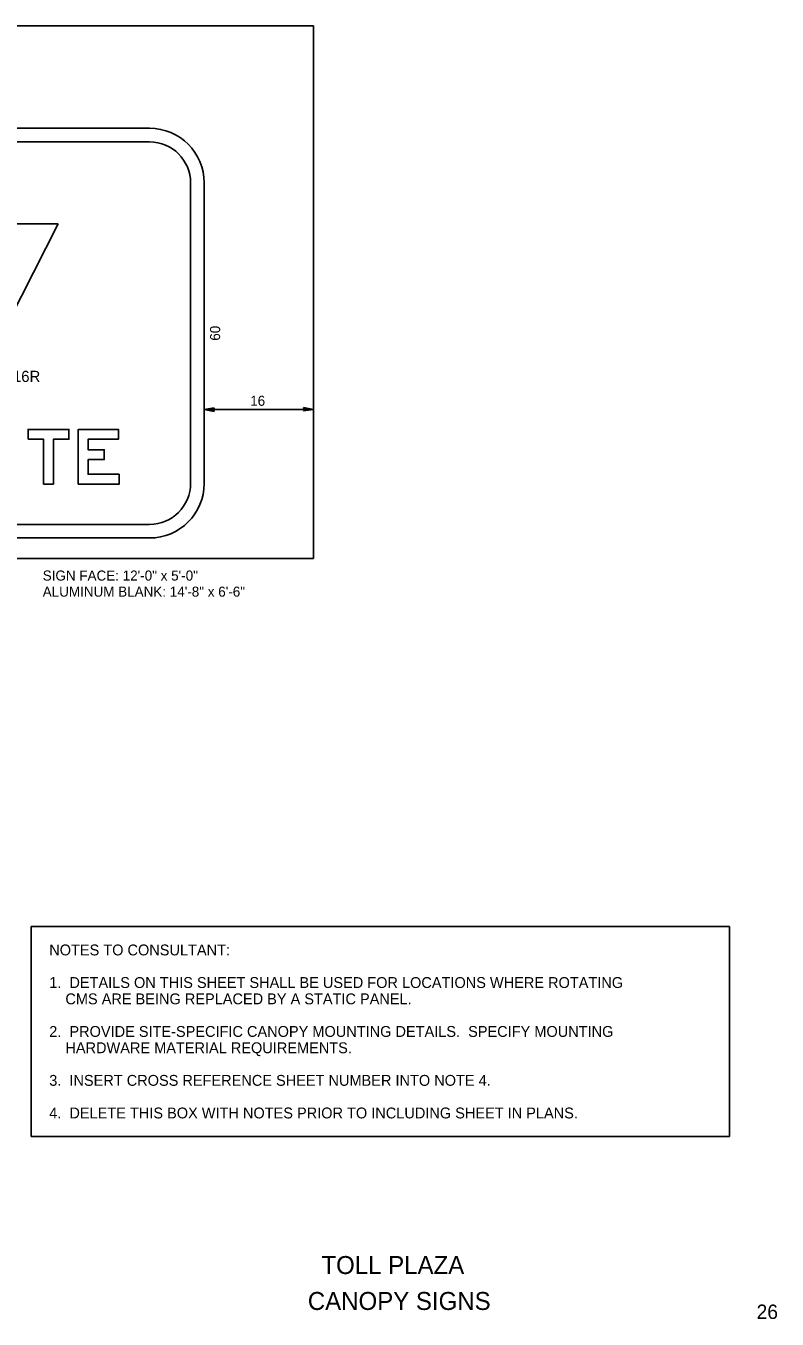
# Model space of a CAD drawing. Extents: x 60714 to 61340, y 9359 to 9729.
# Drawn here: x 61130.7 to 61339.9, y 9369.1 to 9729 of the extents above; entities that cross this region are included whole.
import ezdxf

# ---------------------------------------------------------------- set-up
doc = ezdxf.new("R2010")
doc.units = 0
for name, color, linetype in [('1', 7, 'Continuous'), ('2', 7, 'Continuous'), ('52', 7, 'Continuous'), ('GSBWFill', 7, 'Continuous'), ('SignPanel', 7, 'Continuous'), ('TextAlert', 7, 'Continuous'), ('TextMisc', 7, 'Continuous'), ('TextShtNo', 7, 'Continuous')]:
    doc.layers.add(name, color=color, linetype=linetype)

msp = doc.modelspace()

# ---------------------------------------------------------------- linework, layer by layer
at = {"layer": '1'}
msp.add_line((61180.38, 9622.25), (61210.79, 9622.25), dxfattribs=at)
at = {"layer": '2'}
for p, q in [((60876.38, 9728.97), (61210.79, 9728.97)), ((61210.79, 9580.77), (61210.79, 9728.97)), ((60876.38, 9580.77), (61210.79, 9580.77))]:
    msp.add_line(p, q, dxfattribs=at)
at = {"layer": '52'}
for p, q in [((61180.38, 9622.25), (61183.16, 9622.69)), ((61182.94, 9622.21), (61183.16, 9622.69)), ((61210.79, 9622.25), (61208.02, 9622.79)), ((61208.02, 9622.79), (61208.23, 9622.29)), ((61210.79, 9622.25), (61208.13, 9622.53)), ((61180.38, 9622.25), (61183.04, 9622.44)), ((61180.38, 9622.25), (61183.14, 9621.71)), ((61180.38, 9622.25), (61183.04, 9621.97)), ((61183.14, 9621.71), (61182.94, 9622.21)), ((61208.23, 9622.29), (61208.01, 9621.81)), ((61210.79, 9622.25), (61208.01, 9621.81)), ((61210.79, 9622.25), (61208.13, 9622.06))]:
    msp.add_line(p, q, dxfattribs=at)
at = {"layer": 'GSBWFill'}
for points in [[(61131.33, 9613.93), (61135.66, 9613.93), (61135.66, 9601.47), (61138.4, 9601.47), (61138.4, 9613.93), (61142.73, 9613.93), (61142.73, 9616.67), (61131.33, 9616.67)], [(61131.33, 9613.93), (61135.66, 9613.93), (61135.66, 9601.47), (61138.4, 9601.47), (61138.4, 9613.93), (61142.73, 9613.93), (61142.73, 9616.67), (61131.33, 9616.67)], [(61131.33, 9613.93), (61135.66, 9613.93), (61135.66, 9601.47), (61138.4, 9601.47), (61138.4, 9613.93), (61142.73, 9613.93), (61142.73, 9616.67), (61131.33, 9616.67)], [(61156.72, 9604.2), (61148.05, 9604.2), (61148.05, 9608.29), (61152.54, 9608.29), (61152.54, 9611.03), (61148.05, 9611.03), (61148.05, 9613.93), (61156.49, 9613.93), (61156.49, 9616.67), (61145.32, 9616.67), (61145.32, 9601.47), (61156.72, 9601.47)], [(61156.72, 9604.2), (61148.05, 9604.2), (61148.05, 9608.29), (61152.54, 9608.29), (61152.54, 9611.03), (61148.05, 9611.03), (61148.05, 9613.93), (61156.49, 9613.93), (61156.49, 9616.67), (61145.32, 9616.67), (61145.32, 9601.47), (61156.72, 9601.47)], [(61156.72, 9604.2), (61148.05, 9604.2), (61148.05, 9608.29), (61152.54, 9608.29), (61152.54, 9611.03), (61148.05, 9611.03), (61148.05, 9613.93), (61156.49, 9613.93), (61156.49, 9616.67), (61145.32, 9616.67), (61145.32, 9601.47), (61156.72, 9601.47)]]:
    msp.add_lwpolyline(points, close=True, dxfattribs=at)
at = {"layer": 'SignPanel'}
for p, q in [((60921.98, 9700.47), (61165.18, 9700.47)), ((60921.98, 9696.67), (61165.18, 9696.67)), ((61176.59, 9601.67), (61176.59, 9685.27)), ((61180.39, 9601.67), (61180.39, 9685.27)), ((61031.34, 9673.87), (61139.72, 9673.87)), ((61122.3, 9639.67), (61139.72, 9673.87)), ((60921.98, 9590.27), (61165.18, 9590.27)), ((60921.98, 9586.47), (61165.18, 9586.47))]:
    msp.add_line(p, q, dxfattribs=at)
for centre, radius, start, end in [((61165.18, 9685.27), 15.2, 0, 90), ((61165.18, 9685.27), 11.4, 0, 90), ((61165.18, 9601.67), 15.2, 270, 360), ((61165.18, 9601.67), 11.4, 270, 0)]:
    msp.add_arc(centre, radius, start, end, dxfattribs=at)
at = {"layer": 'TextAlert'}
msp.add_lwpolyline([(61132.23, 9478.35), (61326.59, 9478.35), (61326.59, 9419.97), (61132.23, 9419.97)], close=True, dxfattribs=at)

# ---------------------------------------------------------------- texts
at = {"layer": '1'}
msp.add_text('60', height=2.8, rotation=90, dxfattribs=at).set_placement((61184.8, 9641.36))
for s, height, p in [('LOGO EP-16R', 3.1111, (61107.01, 9629.88)), ('16', 2.8, (61193.18, 9623.25))]:
    msp.add_text(s, height=height, dxfattribs=at).set_placement(p)
at = {"layer": '2'}
for s, p in [('SIGN FACE: 12\'-0" x 5\'-0"', (61135.42, 9574.62)), ('ALUMINUM BLANK: 14\'-8" x 6\'-6"', (61135.42, 9570.14))]:
    msp.add_text(s, height=2.8, dxfattribs=at).set_placement(p)
at = {"layer": 'TextAlert'}
for s, p in [('NOTES TO CONSULTANT:', (61137.23, 9470.33)), ('1.  DETAILS ON THIS SHEET SHALL BE USED FOR LOCATIONS WHERE ROTATING', (61137.23, 9461.26)), ('    CMS ARE BEING REPLACED BY A STATIC PANEL.', (61137.23, 9456.72)), ('2.  PROVIDE SITE-SPECIFIC CANOPY MOUNTING DETAILS.  SPECIFY MOUNTING', (61137.23, 9447.65)), ('    HARDWARE MATERIAL REQUIREMENTS.', (61137.23, 9443.11)), ('3.  INSERT CROSS REFERENCE SHEET NUMBER INTO NOTE 4.', (61137.23, 9434.04)), ('4.  DELETE THIS BOX WITH NOTES PRIOR TO INCLUDING SHEET IN PLANS.', (61137.23, 9424.97))]:
    msp.add_text(s, height=3.024, dxfattribs=at).set_placement(p)
at = {"layer": 'TextMisc'}
for s, p in [('       TOLL PLAZA       ', (61200, 9381.67)), ('      CANOPY SIGNS      ', (61198.07, 9371.67))]:
    msp.add_text(s, height=5, rotation=360, dxfattribs=at).set_placement(p)
at = {"layer": 'TextShtNo'}
msp.add_text('26', height=4, rotation=360, dxfattribs=at).set_placement((61334.15, 9369.17))

doc.saveas('drawing.dxf')
